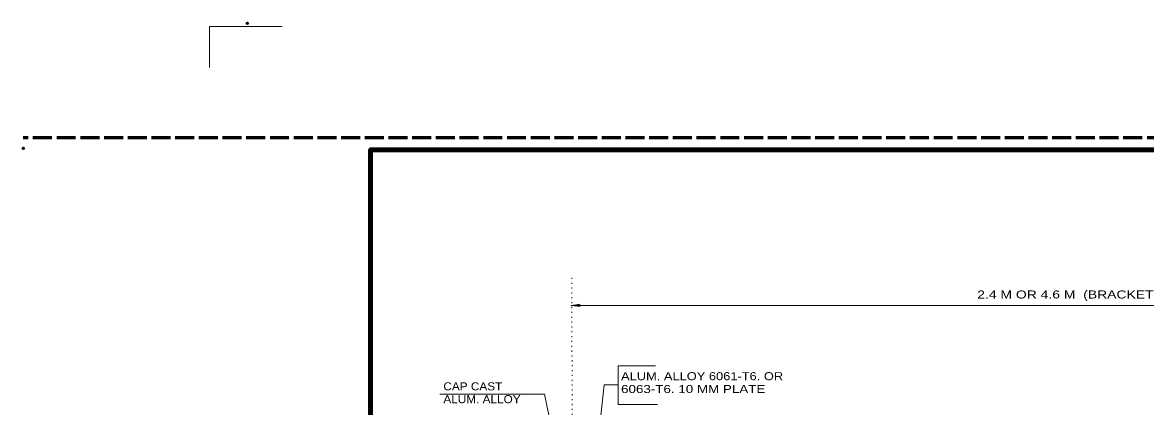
# Model space of a CAD drawing. Extents: x 312583 to 312854, y 144418 to 144597.
# Drawn here: x 312583.5 to 312690.1, y 144560.7 to 144597.2 of the extents above; entities that cross this region are included whole.
import ezdxf

# ---------------------------------------------------------------- set-up
doc = ezdxf.new("R2010")
doc.units = 0
doc.header["$LTSCALE"] = 0.3
doc.header["$PDMODE"] = 32
doc.header["$PDSIZE"] = 0.15
doc.linetypes.add('DOTTED', pattern=[1.5, 0.3, -1.2])
doc.linetypes.add('LONG_DASHED', pattern=[7.5, 6, -1.5])
doc.layers.add('1', color=7, linetype='Continuous', lineweight=35)

msp = doc.modelspace()

# ---------------------------------------------------------------- linework, layer by layer
at = {"layer": '1', "lineweight": 13}
for p, q in [((312601.2, 144596.7846), (312601.2, 144592.8846)), ((312601.2, 144596.7846), (312608.1, 144596.7846)), ((312635.5392, 144570.3242), (312636.4009, 144570.4309)), ((312724.2638, 144570.3242), (312635.5392, 144570.3242)), ((312635.5392, 144570.3242), (312636.4009, 144570.2174)), ((312636.4009, 144570.4309), (312636.1264, 144570.3242)), ((312636.4009, 144570.2174), (312636.1264, 144570.3242)), ((312639.9846, 144564.5826), (312643.5302, 144564.5826)), ((312639.9846, 144560.9302), (312639.9846, 144564.5826)), ((312638.6579, 144562.8059), (312637.2778, 144549.6452)), ((312639.9846, 144562.8059), (312638.6579, 144562.8059)), ((312623.0648, 144561.8986), (312633.0078, 144561.8986)), ((312633.0078, 144561.8986), (312635.0741, 144552.0166)), ((312639.9846, 144560.9302), (312643.7438, 144560.9302)), ((312641.1665, 144560.9302), (312641.868, 144560.9302))]:
    msp.add_line(p, q, dxfattribs=at)
at = {"layer": '1', "linetype": 'LONG_DASHED', "lineweight": 60}
msp.add_line((312851.75, 144586.2246), (312583.526, 144586.2246), dxfattribs=at)
at = {"layer": '1', "lineweight": 158}
msp.add_line((312616.5, 144423.1446), (312616.5, 144585.0846), dxfattribs=at)
at = {"layer": '1', "linetype": 'DOTTED', "lineweight": 13}
msp.add_line((312635.6079, 144572.9396), (312635.6308, 144553.7093), dxfattribs=at)
at = {"layer": '1', "lineweight": 158}
msp.add_lwpolyline([(312849, 144423.0846), (312849, 144585.0846), (312616.5, 144585.0846), (312616.5, 144423.0846)], close=True, dxfattribs=at)
msp.add_lwpolyline([(312616.5, 144585.0846), (312616.5, 144423.0846), (312849, 144423.0846)], dxfattribs=at)
at = {"layer": '1'}
for p in [(312604.8, 144597.0846), (312583.526, 144585.2246)]:
    msp.add_point(p, dxfattribs=at)

# ---------------------------------------------------------------- texts
for s, width, p in [('2.4 M OR 4.6 M  (BRACKET ARM)', 1.3, (312674.0853, 144570.9831)), ('ALUM. ALLOY 6061-T6. OR', 1.2, (312640.2744, 144563.2354)), ('CAP CAST', 1.1, (312623.4079, 144562.2747)), ('6063-T6. 10 MM PLATE', 1.25, (312640.2744, 144562.0179)), ('ALUM. ALLOY', 1.1, (312623.4079, 144561.0572))]:
    msp.add_text(s, height=0.76, dxfattribs=dict(at, width=width)).set_placement(p)

doc.saveas('drawing.dxf')
